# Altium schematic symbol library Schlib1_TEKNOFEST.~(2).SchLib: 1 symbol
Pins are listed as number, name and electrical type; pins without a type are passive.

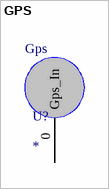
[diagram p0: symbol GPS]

## GPS
designator U?
pins: 0 Gps_In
